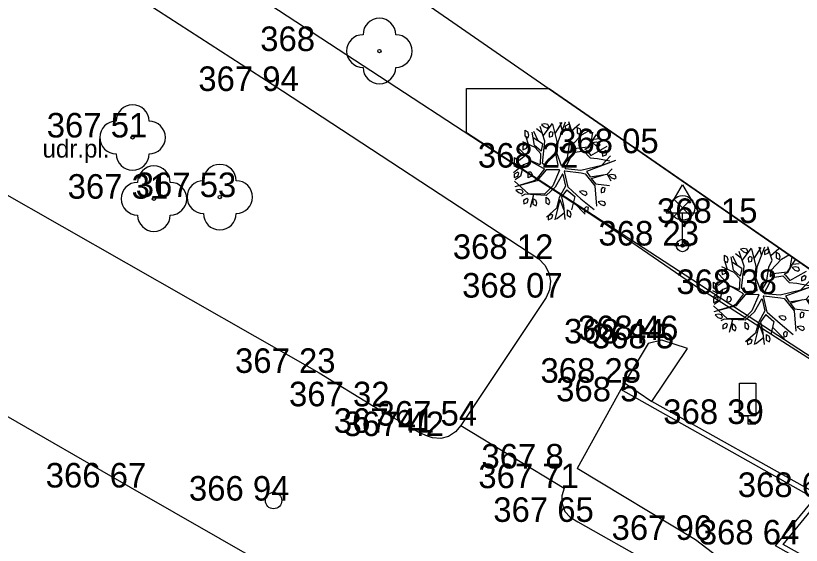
# Model space of a CAD drawing. Extents: x -688316 to -688024, y -973785 to -973591.
# Drawn here: x -688150.19 to -688126.22, y -973686.13 to -973669.95 of the extents above; entities that cross this region are included whole.
import ezdxf

# ---------------------------------------------------------------- set-up
doc = ezdxf.new("R2010")
doc.units = 0
for name, color, linetype in [('Default', 7, 'Continuous'), ('KAM_srafy', 7, 'Continuous'), ('Vrstva 10', 7, 'Continuous'), ('Vrstva 11', 7, 'Continuous'), ('Vrstva 22', 7, 'Continuous'), ('Vrstva 28_Verejne osvetleni', 7, 'Continuous'), ('Vrstva 3', 7, 'Continuous'), ('Vrstva 33', 7, 'Continuous'), ('Vrstva 34', 7, 'Continuous'), ('Vrstva 40', 7, 'Continuous'), ('Vrstva 58', 7, 'Continuous')]:
    doc.layers.add(name, color=color, linetype=linetype)

# ---------------------------------------------------------------- blocks, each defined once
blk = doc.blocks.new('DZ')
at = {"layer": 'Vrstva 34'}
for p, q in [((-5, 10), (0, 18.5)), ((0, 18.5), (5, 10)), ((-5, 10), (5, 10)), ((0, 0), (0, 10)), ((-2.49, 0), (2.49, 0))]:
    blk.add_line(p, q, dxfattribs=at)
blk = doc.blocks.new('POINT_DISPLAY')
at = {"layer": 'Default'}
blk.add_line((0, 0), (0, 0), dxfattribs=at)
blk = doc.blocks.new('SKRIN')
at = {"layer": 'Vrstva 58'}
for p, q in [((-2.5, 2.5), (-2.5, 12.5)), ((-2.5, 12.5), (2.5, 12.5)), ((2.5, 12.5), (2.5, 2.5)), ((2.5, 2.5), (-2.5, 2.5)), ((-2.5, 2.5), (0, 2.5)), ((0, 2.5), (0, 0)), ((0, 0), (2.5, 0))]:
    blk.add_line(p, q, dxfattribs=at)
blk.add_blockref('POINT_DISPLAY', (2.5, 2.5), dxfattribs=at)
blk = doc.blocks.new('STJ')
at = {"layer": 'Vrstva 22'}
blk.add_circle((0, 0), 0.5, dxfattribs=at)
for centre, start, end in [((0, 5), 0, 180), ((-5, 0), 90, 270), ((5, 0), 270, 90), ((0, -5), 180, 0)]:
    blk.add_arc(centre, 5, start, end, dxfattribs=at)
blk = doc.blocks.new('STL')
at = {"layer": 'Vrstva 22'}
blk.add_circle((0, 0), 0.5, dxfattribs=at)
for centre, start, end in [((0, 5), 0, 180), ((-5, 0), 90, 270), ((5, 0), 270, 90), ((0, -5), 180, 0)]:
    blk.add_arc(centre, 5, start, end, dxfattribs=at)
blk = doc.blocks.new('ZKUDR0')
at = {"layer": 'Vrstva 40'}
blk.add_text('udr.pl.', height=5.5, dxfattribs=at).set_placement((-11.71, -3.04))
blk = doc.blocks.new('SV')
at = {"layer": 'Vrstva 28_Verejne osvetleni'}
blk.add_circle((0, 0), 2.5, dxfattribs=at)
blk = doc.blocks.new('LA')
at = {"layer": 'Vrstva 33'}
for p, q in [((-2.65, 14.15), (2.65, 8.85)), ((-2.65, 8.85), (2.65, 14.15)), ((0, 0), (0, 7.75))]:
    blk.add_line(p, q, dxfattribs=at)
for centre, radius in [((0, 11.5), 3.75), ((0, 0), 1.9), ((0, 0), 0.5)]:
    blk.add_circle(centre, radius, dxfattribs=at)
blk = doc.blocks.new('PRO82PP_3')
at = {"layer": 'Default'}
for p, q in [((-2228, 2884), (-2736, 6077)), ((-2133, 6000), (-2450, 5478)), ((-740, 4849), (-2297, 6299)), ((-2133, 6000), (-1887, 5942)), ((-1794, 5478), (-1887, 5942)), ((-1280, 5351), (-740, 6879)), ((-800, 6208), (-294, 6208)), ((-800, 6208), (-388, 5478)), ((81, 5876), (-294, 6208)), ((406, 5661), (1144, 6879)), ((2182, 5213), (1635, 6763)), ((2127, 4443), (2290, 6705)), ((2208, 5835), (3028, 6415)), ((3080, 3487), (4580, 5942)), ((-4672, 2587), (-4344, 4907)), ((-2397, 2844), (-4258, 4840)), ((-2567, 4760), (-3412, 5598)), ((-3246, 3754), (-3130, 5718)), ((-2450, 5478), (-2168, 5013)), ((-2168, 5013), (-1794, 5478)), ((-658, 3689), (-740, 4849)), ((-388, 5478), (175, 5478)), ((-167, 3399), (406, 5661)), ((175, 5478), (81, 5876)), ((2223, 4400), (2236, 5827)), ((2799, 5677), (2424, 5345)), ((2424, 5345), (2987, 5212)), ((3268, 5810), (2799, 5677)), ((2987, 5212), (3455, 5279)), ((3549, 5610), (3268, 5810)), ((3455, 5279), (3549, 5610)), ((4709, 5270), (4392, 4748)), ((4709, 5270), (4955, 5212)), ((5049, 4748), (4955, 5212)), ((5239, 3051), (5731, 4907)), ((-4017, 2007), (-5737, 3573)), ((-5355, 4283), (-5730, 3952)), ((-5730, 3952), (-5168, 3819)), ((-4887, 4416), (-5355, 4283)), ((-5168, 3819), (-4699, 3885)), ((-4605, 4217), (-4887, 4416)), ((-4699, 3885), (-4605, 4217)), ((-3949, 3686), (-4043, 3354)), ((-3574, 3752), (-3949, 3686)), ((-3387, 3222), (-3574, 3752)), ((161, 1485), (-658, 3689)), ((325, 3167), (2127, 4443)), ((570, 2587), (1799, 3573)), ((1799, 3573), (3174, 3155)), ((1868, 3962), (2223, 4400)), ((2039, 3888), (1868, 3962)), ((2049, 3885), (3080, 3487)), ((3174, 3155), (4205, 3620)), ((6730, 4675), (3683, 1079)), ((4205, 3620), (5986, 4217)), ((4392, 4748), (4674, 4283)), ((4674, 4283), (5049, 4748)), ((5239, 3051), (6304, 4211)), ((-4913, 1540), (-6228, 2471)), ((-4918, 2819), (-6065, 2993)), ((-4043, 3354), (-3762, 2890)), ((-3762, 2890), (-3668, 2956)), ((-3668, 2956), (-3387, 3222)), ((-1664, 1208), (-2397, 2844)), ((-1495, 1248), (-2228, 2884)), ((243, 2529), (-167, 3399)), ((243, 2529), (325, 3167)), ((650, -64), (570, 2587)), ((2864, 847), (5239, 3051)), ((6632, 2239), (6877, 3341)), ((7298, 2558), (6923, 2226)), ((7767, 2691), (7298, 2558)), ((8048, 2492), (7767, 2691)), ((7954, 2160), (8048, 2492)), ((-7455, 1961), (-6949, 1961)), ((-7455, 1961), (-7042, 1231)), ((-7042, 1231), (-6480, 1231)), ((-6574, 1629), (-6949, 1961)), ((-6480, 1231), (-6574, 1629)), ((-5082, 673), (-6392, 2239)), ((-4143, 1488), (-5819, 1601)), ((-4143, 1488), (-3771, 383)), ((-2706, -1124), (-4017, 2007)), ((-516, -192), (-1664, 1208)), ((0, 0), (-1495, 1248)), ((82, 36), (161, 1485)), ((4584, 615), (6632, 2239)), ((4830, 499), (6237, 1926)), ((6632, 2239), (7615, 1659)), ((6923, 2226), (7486, 2093)), ((7486, 2093), (7954, 2160)), ((-4836, 441), (-6884, 267)), ((-5943, 347), (-6802, 1137)), ((-6257, 227), (-6574, -295)), ((-6257, 227), (-6011, 169)), ((-5918, -295), (-6011, 169)), ((-3771, 383), (-5082, 673)), ((-3607, 35), (-4836, 441)), ((-2870, -1414), (-3607, 35)), ((720, -108), (2864, 847)), ((800, -459), (3110, 499)), ((3110, 499), (3683, 673)), ((3683, 1079), (4584, 615)), ((3683, 673), (5894, -197)), ((4830, 499), (5813, 93)), ((5813, 93), (7778, 905)), ((7017, 169), (6923, -163)), ((7392, 235), (7017, 169)), ((7579, -295), (7392, 235)), ((-4426, -1646), (-6966, -892)), ((-6574, -295), (-6293, -760)), ((-6293, -760), (-5918, -295)), ((-1887, -1240), (-2706, -1124)), ((-1887, -1240), (-526, -265)), ((-12, -695), (-1723, -1704)), ((63, -733), (325, -3328)), ((734, -1080), (734, -3328)), ((2445, -2358), (782, -539)), ((821, -1047), (2045, -2400)), ((5894, -197), (7615, -2748)), ((6923, -163), (7204, -627)), ((7204, -627), (7298, -561)), ((7298, -561), (7579, -295)), ((-5503, -1327), (-5983, -2458)), ((-4263, -1704), (-5082, -2690)), ((-2870, -1472), (-4426, -1646)), ((-2209, -1704), (-4263, -1704)), ((-2035, -1701), (-2319, -3708)), ((-2209, -1701), (-2035, -1701)), ((-1730, -1701), (-2166, -3847)), ((-1730, -1704), (-1723, -1704)), ((2445, -2358), (4993, -2922)), ((4674, -1755), (4299, -2087)), ((4299, -2087), (4861, -2220)), ((5142, -1623), (4674, -1755)), ((4861, -2220), (5330, -2153)), ((5423, -1822), (5142, -1623)), ((5330, -2153), (5423, -1822)), ((7860, -1755), (7486, -2087)), ((7486, -2087), (8048, -2220)), ((8329, -1623), (7860, -1755)), ((8048, -2220), (8517, -2153)), ((8610, -1822), (8329, -1623)), ((8517, -2153), (8610, -1822)), ((-6892, -2419), (-6386, -2419)), ((-6892, -2419), (-6480, -3149)), ((-6480, -3149), (-5918, -3149)), ((-6011, -2751), (-6386, -2419)), ((-5438, -3560), (-6310, -3560)), ((-5918, -3149), (-6011, -2751)), ((-5082, -2690), (-5819, -4488)), ((-5104, -2717), (-4672, -4430)), ((-3893, -3234), (-3601, -3079)), ((-3747, -3699), (-3893, -3234)), ((-3601, -3079), (-3236, -3337)), ((-3236, -3337), (-3236, -3699)), ((325, -3328), (-167, -5010)), ((734, -3328), (161, -5068)), ((2045, -2400), (2045, -4372)), ((2454, -2806), (2290, -4140)), ((2454, -2806), (4011, -3096)), ((4011, -3096), (4584, -5068)), ((4993, -2922), (7533, -3386)), ((6642, -3547), (6267, -3613)), ((6829, -4078), (6642, -3547)), ((-5320, -4086), (-5636, -4609)), ((-5636, -4609), (-5355, -5073)), ((-5355, -5073), (-4980, -4609)), ((-5320, -4086), (-5074, -4144)), ((-4672, -4430), (-5082, -5300)), ((-4980, -4609), (-5074, -4144)), ((-2166, -3847), (-4609, -6256)), ((-3528, -4061), (-3747, -3699)), ((-2602, -4141), (-3562, -5144)), ((-3236, -3699), (-3528, -4061)), ((-2319, -3708), (-2602, -4141)), ((2045, -4372), (2454, -5996)), ((2290, -4140), (3191, -5126)), ((2290, -4604), (3598, -5702)), ((2290, -4604), (3110, -7620)), ((4257, -3942), (6714, -4662)), ((6267, -3613), (6173, -3945)), ((6173, -3945), (6454, -4410)), ((6454, -4410), (6548, -4343)), ((6548, -4343), (6829, -4078)), ((-2297, -6170), (-5082, -5532)), ((-3534, -5133), (-4120, -5739)), ((161, -5068), (-2706, -6460)), ((-167, -5010), (-2297, -6170)), ((-1559, -5938), (-1068, -7852)), ((231, -5339), (737, -5339)), ((231, -5339), (643, -6069)), ((1112, -5671), (737, -5339)), ((1206, -6069), (1112, -5671)), ((3191, -5126), (4420, -6866)), ((3980, -5405), (4486, -5405)), ((3980, -5405), (4392, -6135)), ((4861, -5737), (4486, -5405)), ((4955, -6135), (4861, -5737)), ((-3856, -6268), (-4231, -6600)), ((-4231, -6600), (-3668, -6732)), ((-3387, -6135), (-3856, -6268)), ((-3668, -6732), (-3200, -6666)), ((-3106, -6334), (-3387, -6135)), ((-3200, -6666), (-3106, -6334)), ((-2706, -6460), (-3034, -6982)), ((-2168, -6931), (-2450, -7396)), ((-1887, -6931), (-2168, -6865)), ((-1794, -7396), (-1887, -6931)), ((-1362, -6467), (-856, -6467)), ((-1362, -6467), (-950, -7197)), ((-481, -6799), (-856, -6467)), ((-388, -7197), (-481, -6799)), ((643, -6069), (1206, -6069)), ((2454, -5996), (1799, -7910)), ((3847, -6054), (3273, -7446)), ((4392, -6135), (4955, -6135)), ((-2450, -7396), (-2168, -7860)), ((-2168, -7860), (-1794, -7396)), ((-950, -7197), (-388, -7197)), ((2272, -7139), (1956, -7661)), ((1956, -7661), (2237, -8126)), ((2237, -8126), (2612, -7661)), ((2272, -7139), (2518, -7197)), ((2612, -7661), (2518, -7197))]:
    blk.add_line(p, q, dxfattribs=at)
for centre, start, end in [((32, 38), 230.1577, 356.89052), ((-555, -224), 305.63007, 39.36151), ((13, -738), 5.76104, 120.5406), ((700, -63), 181.72129, 294.02624), ((784, -1080), 42.11256, 180.00001), ((819, -505), 112.54015, 222.42545)]:
    blk.add_arc(centre, 50, start, end, dxfattribs=at)

msp = doc.modelspace()

# ---------------------------------------------------------------- linework, layer by layer
at = {"layer": 'KAM_srafy'}
for p, q in [((-688136.437, -973673.528), (-688136.437, -973672.178)), ((-688136.437, -973672.178), (-688133.914, -973672.178)), ((-688133.914, -973672.178), (-688110.86, -973688.13)), ((-688133.914, -973672.178), (-688133.914, -973672.178)), ((-688109.92, -973690.8), (-688136.437, -973673.528))]:
    msp.add_line(p, q, dxfattribs=at)
for points in [[(-688109.92, -973690.8), (-688136.437, -973673.528), (-688136.437, -973672.178), (-688133.914, -973672.178)], [(-688133.914, -973672.178), (-688110.86, -973688.13)]]:
    msp.add_lwpolyline(points, dxfattribs=at)
at = {"layer": 'Vrstva 10'}
for p, q in [((-688150.45, -973660.71), (-688131.07, -973674.15)), ((-688152.48, -973665.48), (-688142.05, -973672.25)), ((-688142.05, -973672.25), (-688134.23, -973677.38)), ((-688153.18, -973673.87), (-688140.93, -973680.86)), ((-688146.68, -973684.36), (-688164.44, -973674.16)), ((-688131.07, -973674.15), (-688128, -973676.28)), ((-688128, -973676.28), (-688118.34, -973682.97)), ((-688119.42, -973684.65), (-688129.37, -973678.25)), ((-688131.61, -973681.16), (-688133.06, -973683.78)), ((-688136.61, -973682.47), (-688133.45, -973684.38)), ((-688128.61, -973694.7), (-688146.68, -973684.36)), ((-688133.04, -973685.41), (-688128.02, -973688.23))]:
    msp.add_line(p, q, dxfattribs=at)
for points in [[(-688142.67, -973669.45), (-688132.43, -973676.15), (-688129.37, -973678.25)], [(-688134.23, -973677.38), (-688134.04, -973677.57), (-688133.92, -973677.8), (-688133.87, -973678.06), (-688133.9, -973678.32), (-688134, -973678.56), (-688136.61, -973682.47)], [(-688140.93, -973680.86), (-688139.27, -973681.88), (-688137.86, -973682.69)], [(-688123.045, -973684.829), (-688123.471, -973684.566), (-688125.098, -973687.211), (-688126.999, -973686.143), (-688125.809, -973684.693), (-688131.727, -973681.371)], [(-688123.52, -973684.36), (-688125.15, -973687.01), (-688126.77, -973686.1), (-688125.58, -973684.65), (-688130.78, -973681.73)], [(-688136.61, -973682.47), (-688136.77, -973682.66), (-688136.98, -973682.8), (-688137.22, -973682.86), (-688137.47, -973682.84), (-688137.62, -973682.79), (-688137.86, -973682.69)], [(-688117.05, -973688.61), (-688118.95, -973691.55), (-688122.71, -973689.32), (-688123.6, -973690.77), (-688125.86, -973688.7), (-688129.44, -973685.96), (-688133.06, -973683.78)], [(-688133.45, -973684.38), (-688133.52, -973684.61), (-688133.51, -973684.86), (-688133.43, -973685.09), (-688133.27, -973685.27), (-688133.04, -973685.41)]]:
    msp.add_lwpolyline(points, dxfattribs=at)
at = {"layer": 'Vrstva 11'}
msp.add_lwpolyline([(-688130.78, -973681.73), (-688129.69, -973680.11), (-688130.47, -973679.86), (-688130.89, -973679.96), (-688131.61, -973681.16), (-688130.78, -973681.73)], dxfattribs=at)

# ---------------------------------------------------------------- block references
at = {"layer": 'Default', "xscale": 0.00020177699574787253, "yscale": 0.0002017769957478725, "rotation": -29.299057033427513}
for p in [(-688133.53, -973674.532), (-688127.453, -973678.345)]:
    msp.add_blockref('PRO82PP_3', p, dxfattribs=at)
at = {"layer": 'Vrstva 22', "xscale": 0.1, "yscale": 0.10000000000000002}
for name, p in [('STL', (-688139.09, -973671.03)), ('STJ', (-688146.62, -973673.67)), ('STJ', (-688145.97, -973675.54)), ('STJ', (-688143.96, -973675.49))]:
    msp.add_blockref(name, p, dxfattribs=at)
at = {"layer": 'Vrstva 28_Verejne osvetleni', "xscale": 0.1, "yscale": 0.10000000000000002}
msp.add_blockref('SV', (-688142.32, -973684.76), dxfattribs=at)
at = {"layer": 'Vrstva 33', "xscale": 0.1, "yscale": 0.10000000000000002}
msp.add_blockref('LA', (-688129.84, -973676.97), dxfattribs=at)
at = {"layer": 'Vrstva 34', "xscale": 0.1, "yscale": 0.10000000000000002}
msp.add_blockref('DZ', (-688129.84, -973676.97), dxfattribs=at)
msp.add_blockref('DZ', (-688129.84, -973676.97), dxfattribs=at)
msp.add_blockref('DZ', (-688129.84, -973676.97), dxfattribs=at)
msp.add_blockref('DZ', (-688129.84, -973676.97), dxfattribs=at)
at = {"layer": 'Vrstva 40', "xscale": 0.1, "yscale": 0.10000000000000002}
msp.add_blockref('ZKUDR0', (-688148.2, -973673.98), dxfattribs=at)
at = {"layer": 'Vrstva 58', "xscale": 0.1, "yscale": 0.10000000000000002}
msp.add_blockref('SKRIN', (-688127.85, -973682.42), dxfattribs=at)
msp.add_blockref('SKRIN', (-688127.85, -973682.42), dxfattribs=at)
msp.add_blockref('SKRIN', (-688127.85, -973682.42), dxfattribs=at)
msp.add_blockref('SKRIN', (-688127.85, -973682.42), dxfattribs=at)

# ---------------------------------------------------------------- texts
at = {"layer": 'Vrstva 3'}
for s, p in [('368    ', (-688142.727, -973671.03)), ('368    ', (-688142.727, -973671.03)), ('368    ', (-688142.727, -973671.03)), ('368    ', (-688142.727, -973671.03)), ('368    ', (-688142.727, -973671.03)), ('368    ', (-688142.727, -973671.03)), ('368    ', (-688142.727, -973671.03)), ('367 94 ', (-688144.616, -973672.25)), ('367 94 ', (-688144.616, -973672.25)), ('367 94 ', (-688144.616, -973672.25)), ('367 94 ', (-688144.616, -973672.25)), ('367 94 ', (-688144.616, -973672.25)), ('367 94 ', (-688144.616, -973672.25)), ('367 94 ', (-688144.616, -973672.25)), ('367 51 ', (-688149.241, -973673.67)), ('367 51 ', (-688149.241, -973673.67)), ('367 51 ', (-688149.241, -973673.67)), ('367 51 ', (-688149.241, -973673.67)), ('367 51 ', (-688149.241, -973673.67)), ('367 51 ', (-688149.241, -973673.67)), ('367 51 ', (-688149.241, -973673.67)), ('368 05 ', (-688133.636, -973674.15)), ('368 05 ', (-688133.636, -973674.15)), ('368 05 ', (-688133.636, -973674.15)), ('368 05 ', (-688133.636, -973674.15)), ('368 05 ', (-688133.636, -973674.15)), ('368 05 ', (-688133.636, -973674.15)), ('368 05 ', (-688133.636, -973674.15)), ('368 22 ', (-688136.086, -973674.59)), ('368 22 ', (-688136.086, -973674.59)), ('368 22 ', (-688136.086, -973674.59)), ('368 22 ', (-688136.086, -973674.59)), ('368 22 ', (-688136.086, -973674.59)), ('368 22 ', (-688136.086, -973674.59)), ('368 22 ', (-688136.086, -973674.59)), ('367 31 ', (-688148.603, -973675.54)), ('367 31 ', (-688148.603, -973675.54)), ('367 31 ', (-688148.603, -973675.54)), ('367 31 ', (-688148.603, -973675.54)), ('367 31 ', (-688148.603, -973675.54)), ('367 31 ', (-688148.603, -973675.54)), ('367 31 ', (-688148.603, -973675.54)), ('367 53 ', (-688146.526, -973675.49)), ('367 53 ', (-688146.526, -973675.49)), ('367 53 ', (-688146.526, -973675.49)), ('367 53 ', (-688146.526, -973675.49)), ('367 53 ', (-688146.526, -973675.49)), ('367 53 ', (-688146.526, -973675.49)), ('367 53 ', (-688146.526, -973675.49)), ('368 15 ', (-688130.621, -973676.28)), ('368 15 ', (-688130.621, -973676.28)), ('368 15 ', (-688130.621, -973676.28)), ('368 15 ', (-688130.621, -973676.28)), ('368 15 ', (-688130.621, -973676.28)), ('368 15 ', (-688130.621, -973676.28)), ('368 15 ', (-688130.621, -973676.28)), ('368 23 ', (-688132.406, -973676.97)), ('368 23 ', (-688132.406, -973676.97)), ('368 23 ', (-688132.406, -973676.97)), ('368 23 ', (-688132.406, -973676.97)), ('368 23 ', (-688132.406, -973676.97)), ('368 23 ', (-688132.406, -973676.97)), ('368 23 ', (-688132.406, -973676.97)), ('368 12 ', (-688136.851, -973677.38)), ('368 12 ', (-688136.851, -973677.38)), ('368 12 ', (-688136.851, -973677.38)), ('368 12 ', (-688136.851, -973677.38)), ('368 12 ', (-688136.851, -973677.38)), ('368 12 ', (-688136.851, -973677.38)), ('368 12 ', (-688136.851, -973677.38)), ('368 38 ', (-688130.028, -973678.45)), ('368 38 ', (-688130.028, -973678.45)), ('368 38 ', (-688130.028, -973678.45)), ('368 38 ', (-688130.028, -973678.45)), ('368 38 ', (-688130.028, -973678.45)), ('368 38 ', (-688130.028, -973678.45)), ('368 38 ', (-688130.028, -973678.45)), ('368 07 ', (-688136.566, -973678.56)), ('368 07 ', (-688136.566, -973678.56)), ('368 07 ', (-688136.566, -973678.56)), ('368 07 ', (-688136.566, -973678.56)), ('368 07 ', (-688136.566, -973678.56)), ('368 07 ', (-688136.566, -973678.56)), ('368 07 ', (-688136.566, -973678.56)), ('368 46 ', (-688133.036, -973679.86)), ('368 46 ', (-688133.036, -973679.86)), ('368 46 ', (-688133.036, -973679.86)), ('368 46 ', (-688133.036, -973679.86)), ('368 46 ', (-688133.036, -973679.86)), ('368 46 ', (-688133.036, -973679.86)), ('368 46 ', (-688133.036, -973679.86)), ('368 44 ', (-688133.456, -973679.96)), ('368 44 ', (-688133.456, -973679.96)), ('368 44 ', (-688133.456, -973679.96)), ('368 44 ', (-688133.456, -973679.96)), ('368 44 ', (-688133.456, -973679.96)), ('368 44 ', (-688133.456, -973679.96)), ('368 44 ', (-688133.456, -973679.96)), ('368 5  ', (-688132.607, -973680.11)), ('368 5  ', (-688132.607, -973680.11)), ('368 5  ', (-688132.607, -973680.11)), ('368 5  ', (-688132.607, -973680.11)), ('368 5  ', (-688132.607, -973680.11)), ('368 5  ', (-688132.607, -973680.11)), ('368 5  ', (-688132.607, -973680.11)), ('367 23 ', (-688143.496, -973680.86)), ('367 23 ', (-688143.496, -973680.86)), ('367 23 ', (-688143.496, -973680.86)), ('367 23 ', (-688143.496, -973680.86)), ('367 23 ', (-688143.496, -973680.86)), ('367 23 ', (-688143.496, -973680.86)), ('367 23 ', (-688143.496, -973680.86)), ('368 28 ', (-688134.176, -973681.16)), ('368 28 ', (-688134.176, -973681.16)), ('368 28 ', (-688134.176, -973681.16)), ('368 28 ', (-688134.176, -973681.16)), ('368 28 ', (-688134.176, -973681.16)), ('368 28 ', (-688134.176, -973681.16)), ('368 28 ', (-688134.176, -973681.16)), ('368 5  ', (-688133.697, -973681.73)), ('368 5  ', (-688133.697, -973681.73)), ('368 5  ', (-688133.697, -973681.73)), ('368 5  ', (-688133.697, -973681.73)), ('368 5  ', (-688133.697, -973681.73)), ('368 5  ', (-688133.697, -973681.73)), ('368 5  ', (-688133.697, -973681.73)), ('367 32 ', (-688141.848, -973681.88)), ('367 32 ', (-688141.848, -973681.88)), ('367 32 ', (-688141.848, -973681.88)), ('367 32 ', (-688141.848, -973681.88)), ('367 32 ', (-688141.848, -973681.88)), ('367 32 ', (-688141.848, -973681.88)), ('367 32 ', (-688141.848, -973681.88)), ('367 54 ', (-688139.176, -973682.47)), ('367 54 ', (-688139.176, -973682.47)), ('367 54 ', (-688139.176, -973682.47)), ('367 54 ', (-688139.176, -973682.47)), ('367 54 ', (-688139.176, -973682.47)), ('367 54 ', (-688139.176, -973682.47)), ('367 54 ', (-688139.176, -973682.47)), ('368 39 ', (-688130.428, -973682.42)), ('368 39 ', (-688130.428, -973682.42)), ('368 39 ', (-688130.428, -973682.42)), ('368 39 ', (-688130.428, -973682.42)), ('368 39 ', (-688130.428, -973682.42)), ('368 39 ', (-688130.428, -973682.42)), ('368 39 ', (-688130.428, -973682.42)), ('367 41 ', (-688140.481, -973682.69)), ('367 41 ', (-688140.481, -973682.69)), ('367 41 ', (-688140.481, -973682.69)), ('367 41 ', (-688140.481, -973682.69)), ('367 41 ', (-688140.481, -973682.69)), ('367 41 ', (-688140.481, -973682.69)), ('367 41 ', (-688140.481, -973682.69)), ('367 42 ', (-688140.186, -973682.79)), ('367 42 ', (-688140.186, -973682.79)), ('367 42 ', (-688140.186, -973682.79)), ('367 42 ', (-688140.186, -973682.79)), ('367 42 ', (-688140.186, -973682.79)), ('367 42 ', (-688140.186, -973682.79)), ('367 42 ', (-688140.186, -973682.79)), ('367 8  ', (-688135.977, -973683.78)), ('367 8  ', (-688135.977, -973683.78)), ('367 8  ', (-688135.977, -973683.78)), ('367 8  ', (-688135.977, -973683.78)), ('367 8  ', (-688135.977, -973683.78)), ('367 8  ', (-688135.977, -973683.78)), ('367 8  ', (-688135.977, -973683.78)), ('366 67 ', (-688149.272, -973684.36)), ('366 67 ', (-688149.272, -973684.36)), ('366 67 ', (-688149.272, -973684.36)), ('366 67 ', (-688149.272, -973684.36)), ('366 67 ', (-688149.272, -973684.36)), ('366 67 ', (-688149.272, -973684.36)), ('366 67 ', (-688149.272, -973684.36)), ('367 71 ', (-688136.071, -973684.38)), ('367 71 ', (-688136.071, -973684.38)), ('367 71 ', (-688136.071, -973684.38)), ('367 71 ', (-688136.071, -973684.38)), ('367 71 ', (-688136.071, -973684.38)), ('367 71 ', (-688136.071, -973684.38)), ('367 71 ', (-688136.071, -973684.38)), ('368 65 ', (-688128.155, -973684.65)), ('368 65 ', (-688128.155, -973684.65)), ('368 65 ', (-688128.155, -973684.65)), ('368 65 ', (-688128.155, -973684.65)), ('368 65 ', (-688128.155, -973684.65)), ('368 65 ', (-688128.155, -973684.65)), ('368 65 ', (-688128.155, -973684.65)), ('366 94 ', (-688144.903, -973684.76)), ('366 94 ', (-688144.903, -973684.76)), ('366 94 ', (-688144.903, -973684.76)), ('366 94 ', (-688144.903, -973684.76)), ('366 94 ', (-688144.903, -973684.76)), ('366 94 ', (-688144.903, -973684.76)), ('366 94 ', (-688144.903, -973684.76)), ('367 65 ', (-688135.615, -973685.41)), ('367 65 ', (-688135.615, -973685.41)), ('367 65 ', (-688135.615, -973685.41)), ('367 65 ', (-688135.615, -973685.41)), ('367 65 ', (-688135.615, -973685.41)), ('367 65 ', (-688135.615, -973685.41)), ('367 65 ', (-688135.615, -973685.41)), ('367 96 ', (-688132.006, -973685.96)), ('367 96 ', (-688132.006, -973685.96)), ('367 96 ', (-688132.006, -973685.96)), ('367 96 ', (-688132.006, -973685.96)), ('367 96 ', (-688132.006, -973685.96)), ('367 96 ', (-688132.006, -973685.96)), ('367 96 ', (-688132.006, -973685.96)), ('368 64 ', (-688129.345, -973686.1)), ('368 64 ', (-688129.345, -973686.1)), ('368 64 ', (-688129.345, -973686.1)), ('368 64 ', (-688129.345, -973686.1)), ('368 64 ', (-688129.345, -973686.1)), ('368 64 ', (-688129.345, -973686.1)), ('368 64 ', (-688129.345, -973686.1))]:
    msp.add_text(s, height=0.75, dxfattribs=at).set_placement(p)

doc.saveas('drawing.dxf')
